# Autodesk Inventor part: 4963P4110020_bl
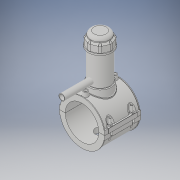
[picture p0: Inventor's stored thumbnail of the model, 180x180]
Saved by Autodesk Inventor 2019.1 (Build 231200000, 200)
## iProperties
Created: 2017-07
Part Number: 4963P4110020_bl
Material: Generic
Document SubType Name: Modeling
Designer: KIM
Density: 1 g/cm^3
Appearance: Default
Author: KIM
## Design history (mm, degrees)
derived "4963P4.ipt"
feature "Solid1::4963P4.ipt" dims "ScaleForDerivedMember" = 10
feature "Solid2::4963P4.ipt" dims "ScaleForDerivedMember" = 10
feature "Solid3::4963P4.ipt" dims "ScaleForDerivedMember" = 10
tag "TaggingFeature1"
body "Solid1"
body "Solid2"
body "Solid3"
other parameters: "d2" = 148 [user parameter], "d3" = 27.5 [user parameter], "d4" = 118 [user parameter], "d5" = 0 [user parameter], "d6" = 0.1 [user parameter], "d8" = 0 [user parameter], "d19" = 6 [user parameter], "d20" = 6 [user parameter], "d21" = 70.8 [user parameter], "d23" = 0 [user parameter], "d24" = 35.4 [user parameter], "d26" = 0 [user parameter], "d27" = 3 [user parameter], "d28" = 3 [user parameter], "d29" = 3 [user parameter], "d30" = 36.66667 [user parameter], "d31" = 6 [user parameter], "d32" = 0 [user parameter], "d33" = 0 [user parameter], "d34" = 0.6 [user parameter], "d40" = 74.36 [user parameter], "d41" = 77 [user parameter], "d43" = 0 [user parameter], "d45" = 0 [user parameter], "d47" = 142.3 [user parameter], "d70" = 15 [user parameter], "d72" = 0 [user parameter], "d73" = 6 [user parameter], "d75" = 5 [user parameter], "d76" = 0 [user parameter], "d77" = 5.5 [user parameter], "d78" = 85 [user parameter], "d79" = 15 [user parameter], "d80" = 47.2 [user parameter], "d82" = 5 deg [user parameter], "d84" = 4 [user parameter], "d85" = 14 [user parameter], "d86" = 0 [user parameter], "d87" = 3 [user parameter], "d88" = 0 [user parameter], "d89" = 1 [user parameter], "d90" = 1 [user parameter], "d91" = 94.4 [user parameter], "d92" = 0 [user parameter], "d93" = 0.5 [user parameter], "d94" = 57.89474 [user parameter], "d96" = 145.86 [user parameter], "d97" = 2.36 [user parameter], "d98" = 0 [user parameter], "d102" = 1.1 [user parameter], "d120" = 140 deg [user parameter], "d121" = 24.228 [user parameter], "d122" = 20 deg [user parameter], "d123" = 286 [user parameter], "d124" = 85.8 [user parameter], "d126" = 0 [user parameter], "d143" = 113.3 [user parameter], "d145" = 25.38462 [user parameter], "d149" = 1.65 [user parameter], "d150" = 27.92308 [user parameter], "d153" = 118 [user parameter], "d154" = 0 [user parameter], "d156" = 71.5 [user parameter], "d157" = 160 deg [user parameter], "d159" = 6.6 [user parameter], "d161" = 1.65 [user parameter], "d162" = 70.8 [user parameter], "d163" = 0 [user parameter], "d164" = 55 [user parameter], "d167" = 11 [user parameter], "d168" = 69.7561 [user parameter], "d170" = 3.75 [user parameter], "d172" = 0 [user parameter], "d173" = 1 [user parameter], "d175" = 55 [user parameter], "d176" = 20 deg [user parameter], "d177" = 7.7 [user parameter], "d178" = 33 [user parameter], "d180" = 0 [user parameter], "d183" = 13.2 [user parameter], "d184" = 6.16 [user parameter], "d185" = 38.35 [user parameter], "d186" = 38.35 [user parameter], "d187" = 71.5 [user parameter], "d188" = 9.9 [user parameter], "d189" = 7.7 [user parameter], "d190" = 0 [user parameter], "d191" = 107.25 [user parameter], "d193" = 8 [user parameter], "d194" = 4.13 [user parameter], "d195" = 90 deg [user parameter], "d197" = 0 [user parameter], "d199" = 0 [user parameter], "d200" = 16.5 [user parameter], "d202" = 0 [user parameter], "d203" = 177 [user parameter], "d204" = 73.15 [user parameter], "d205" = 53.9 [user parameter], "d206" = 65.45 [user parameter], "d207" = 132.75 [user parameter], "d208" = 138.06 [user parameter], "d209" = 164.61 [user parameter], "d210" = 66.22 [user parameter], "d211" = 77 [user parameter], "d212" = 61.6 [user parameter], "d213" = 36 [user parameter], "d216" = 0 [user parameter], "d217" = 11 [user parameter], "d218" = 11 [user parameter], "d219" = 2.2 [user parameter], "d224" = 0 [user parameter], "d227" = 16 [user parameter], "d228" = 125 [user parameter], "d230" = 6.6 [user parameter], "B_" = 148 [user parameter], "L_" = 118 [user parameter], "d_t" = 6 [user parameter], "H_2" = 177 [user parameter], "H_" = 125 [user parameter], "d1" = 143 [user parameter]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
